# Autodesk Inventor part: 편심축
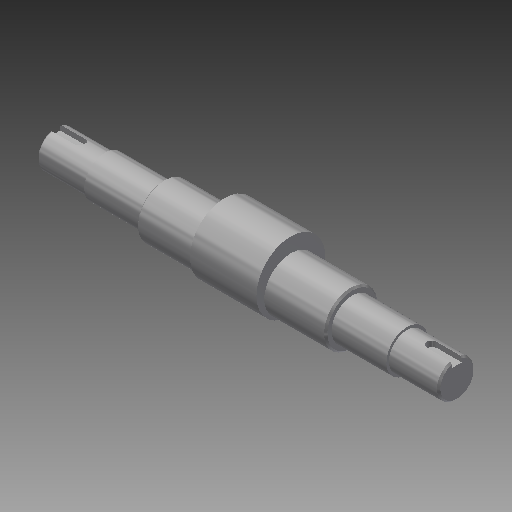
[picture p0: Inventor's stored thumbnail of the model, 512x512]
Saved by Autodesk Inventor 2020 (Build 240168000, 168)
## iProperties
Created: 2015-10
Part Number: 편심축
Document SubType Name: Modeling
Designer: mdu
Density: 1 g/cm^3
Material: 강철, 연강
Mass: 168.947 g
Surface Area: 248.524 cm^2
Volume: 168.947 cm^3
Appearance: 강철
Author: mdu
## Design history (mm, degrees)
sketch "스케치1"
  geometry: L1 (-20.5, -41.331)-(-20.5, 32.669) reference; L2 (7.5, -30.031)-(7.5, 21.369) reference; L3 (135.5, -30.331)-(135.5, 21.669) reference; L4 (121.5, 21.369)-(121.5, -30.031) reference; L5 (184.5, -4.331)-(-57.5, -4.331); L6 (184.5, -4.331)-(184.5, 6.669); L7 (154.5, 8.169)-(121.5, 8.169); L8 (121.5, 8.169)-(121.5, 11.669); L9 (121.5, 11.669)-(7.5, 11.669); L10 (7.5, 11.669)-(7.5, 8.169); L11 (7.5, 8.169)-(-27.5, 8.169); L12 (-27.5, 8.169)-(-27.5, 6.669); L13 (-27.5, 6.669)-(-57.5, 6.669); L14 (-57.5, 6.669)-(-57.5, -4.331); L15 (154.5, 8.169)-(154.5, 6.669); L16 (154.5, 6.669)-(184.5, 6.669); C1 r 32.5 at (64.5, -4.331) reference; 1 further point
  constraints: 24 end point, 8 perpendicular, 5 point on line, 3 parallel, 2 collinear
  dimensions: "d1" = 25 diameter of L11 L5; "d2" = 32 diameter of L9 L5; "d3" = 22 diameter of L13 L5; "d4" = 35 distance of L10.end L11.end; "d5" = 30 distance of L12.end L13.end; "d15" = 33 distance of L7.start L7.end; "d26" = 30 distance of L15.end L6.end
revolve "회전1" sketch "스케치1" stored, may be unused: angle "d6" = 90 deg
node "작업 평면1"
sketch "스케치2"
  geometry: C1 r 16 at (0, 0) reference; C2 r 20.75 at (0, 4)
  constraints: 1 centre point, 1 vertical alignment
  dimensions: "d34" = 4 distance of C2.centre C1.centre; "d35" = 41.5 diameter of C2
extrude "돌출1" join sketch "스케치2" stored distance "d9" = 40; taper "d10" = 0 deg
chamfer "모따기1" distance "d11" = 1; stored, may be unused: second distance "d12" = 2, angle "d13" = 45 deg
node "작업 평면2"
sketch "스케치3"
  geometry: L1 (-15, -10)-(-15, 10) reference; L2 (-15, 3)-(0, 3); L3 (0, -3)-(-15, -3); A1 r 3 centre (0, 0) between (0, -3) and (0, 3); 2 further points
  constraints: 4 end point, 2 perpendicular, 2 point on circle, 2 point on line, 2 tangent, 1 centre point, 1 horizontal alignment, 1 midpoint
  dimensions: "d16" = 18 dimension on A1 L1; "d17" = 6 distance between parallel lines of L3 L2
extrude "돌출2" cut sketch "스케치3" distance "d18" = 3.5; taper "d19" = 0 deg
node "작업 평면3"
node "솔리드1"
mirror "대칭1"
node "참조1"
node "참조2"
node "참조3"
node "참조4"
node "참조5"
other parameters: "d30" = 35
